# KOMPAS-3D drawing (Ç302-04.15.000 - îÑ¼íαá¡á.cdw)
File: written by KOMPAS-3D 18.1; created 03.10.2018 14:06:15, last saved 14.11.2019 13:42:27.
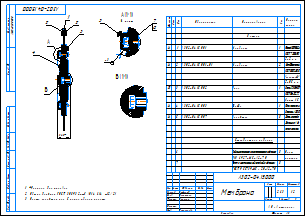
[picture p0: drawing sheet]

Sheet 1: A3, landscape

Document properties: Автор: Милов; Масса: 2.62614; Полное имя файла: ..\А302-01.15.000 - Мембрана.a3d

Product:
- Part/product: (unnamed)
  - Component: Мембрана  | designation А302-04.15.001  | pos. 1  | Раздел спецификации: Детали; Форматы листов документа: А4; Примечание: Пластина ІФ-IІ ТМКЩ-C-4 / ГОСТ 7338-90 / S=2 мм
  - Component: Мембрана  | designation А302-04.15.001-01  | pos. 2  | Раздел спецификации: Детали; Форматы листов документа: А4; Примечание: Лист Фторопласт-4 /  ГОСТ 10007-80 Е / "каленный" / S=0,5 мм
  - Component: Упор  | designation А302-04.15.002  | pos. 3  | Раздел спецификации: Детали; Форматы листов документа: А3; Примечание: Сталь 12Х18Н10Т / ГОСТ 5632-72 / Лист 15
  - Component: Шайба  | designation А302-04.15.003  | pos. 4  | Раздел спецификации: Детали; Форматы листов документа: А4; Примечание: Полипропилен / Стержень @2~300
  - Component: Заглушка  | designation А302-04.15.007  | pos. 5  | Раздел спецификации: Детали; Форматы листов документа: А4; Примечание: Деталь заготовка  / Заглушка @2~16 / полипропилен
  - Component: Гайка шестигранная самостопорящаяся с фланцем / DIN 6927-M5-A2-70  | pos. 6  | Раздел спецификации: Стандартные изделия; Примечание: Нерж. / насечки
  - Component: Болт с шестигранной головкой с фланцем  / ГОСТ Р 55739-М5 x 20-A2-70  | pos. 7  | Раздел спецификации: Стандартные изделия

Title block, sheet 1: Наименование: Мембрана; designation: А302-04.15.000; Масса: 2,63; scale: 1:2; Количество листов документа: 1; organisation: АО «Астерион»; Форматы листов документа: A3; stored path: \\192.168.87.28\Konstructor_doc\Мембранные насосы\Мембранный электропривод\А302-00.00.000 - ASTRA-302 (МЭ200)\3Д ПВХ\А302-01.15.000 - Мембрана.cdw; Разработал: Лифлянд; Проверил: Борисенко; Т. контр.: Лучихин; Утвердил: Григорьева

Views: Вид 1, Местный разрез 1, Вид:2, Выносной элемент 3, Выносной элемент А, Выносной элемент, Выносной элемент Б
Referenced files in D:\Мембранные насосы\Мембранный электропривод\А302-00.00.000 - ASTRA-302 (МЭ200)\3Д ПВХ\: А302-01.15.001-01- Мембрана.m3d, А302-01.15.007 - Заглушка.m3d, А302-01.15.001 - Мембрана.m3d, А302-01.15.002 - Упор.a3d, А302-01.15.003 - Шайба.m3d, А302-01.15.000 - Мембрана.a3d, А302-01.15.001 - Мембрана.cdw, А302-01.15.002 - Упор.m3d, А302-01.15.008 - Кольцо плоское Ф4.m3d, А302-01.15.008 - Кольцо плоское уплотнительное 5-13-10 Ф4.cdw, А302-01.15.009 - Кольцо плоское Ф4.m3d, А302-01.15.007 - Заглушка.cdw, А302-01.15.011 - Заглушка резьбовая.m3d, А302-01.15.011 - Заглушка резьбовая.cdw
Referenced files in Z:\Мембранные насосы\Мембранный электропривод\А302-00.00.000 - ASTRA-302 (МЭ200)\3Д ПВХ\: А302-01.15.000 - Мембрана.a3d, А302-01.15.008 - Кольцо плоское Ф4.m3d
Referenced files in D:\2 Стандартные изделия 3D\Гайки\DIN 6927\: Гайка шестигранная самостопорящаяся с фланцем DIN 6927-M5 - A2-70.m3d
Referenced files in \\192.168.87.28\Konstructor_doc\Мембранные насосы\Мембранный электропривод\А302-00.00.000 - ASTRA-302 (МЭ200)\3Д ПВХ\: А302-01.15.011 - Заглушка резьбовая.cdw
Referenced files in D:\Мембранные насосы\Мембранный электропривод\А302-00.00.000 - ASTRA-302 (МЭ200)\А302-04.00.000 - Мембранный насос ASTRA-302-PP\: А302-02.15.002 - Упор.cdw
Referenced files in C:\Program Files\ASCON\KOMPAS-3D v18\Libs\PartLib\DATA\VAULT\methods\kompas\3d\: PLib_Bolt_1_ISO_1100.m3d, PLib_Nut_ISO_1100.m3d
Referenced files in C:\Program Files\ASCON\KOMPAS-3D V16\Libs\PartLib\DATA\vault\Methods\Kompas\3D\: PLib_Nut_ISO_1100.m3d, PLib_Bolt_1_ISO_1100.m3d
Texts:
  Шайба
  Упор
  Болт с шестигранной головкой с фланцем
  ГОСТ Р  55739-М5 x 25-A2-70
  ГОСТ
  Нерж.
  Нержавеющая сталь
  Гайка шестигранная самостопорящаяся с фланцем
  DIN 6927-M5-A2-70
  Гайка
  шестигранная
  самостопорящаяся
  фланцем
  DIN
  насечки
  Нерж. / насечки
  Кольцо плоское
  уплотнительное 5-13-10 Ф4
  Кольцо плоское  / уплотнительное 5-13-10 Ф4
  ГОСТ Р  55739-М8 x 30-A2-70
  Кольцо плоское Ф4
  Заглушка
  Заглушка резьбовая
  Лента ФУМ
  Лента
  ФУМ
  3D_Doc-graphic.lyt,1.000000-4294967295-203648116615
  Болт с шестигранной головкой с фланцем ГОСТ Р 55739-М5 x 20-A2-70
  Болт
  шестигранной
  головкой
  Пластина ІФ-IІ ТМКЩ-C-4
  ГОСТ 7338-90
  Пластина ІФ-IІ ТМКЩ-C-4 / ГОСТ 7338-90 / S=2 мм
  Лист Фторопласт-4
  ГОСТ 10007-80 Е
  "каленный"
  Лист Фторопласт-4 /  ГОСТ 10007-80 Е / "каленный" / S=0,5 мм
  Сталь 12Х18Н10Т
  ГОСТ 5632-72
  Лист 15
  Сталь 12Х18Н10Т / ГОСТ 5632-72 / Лист 15
  Полипропилен
  Стержень  300
  Полипропилен / Стержень @2~300
  Деталь заготовка
  Заглушка  16
  полипропилен
  Деталь заготовка  / Заглушка @2~16 / полипропилен
  ГОСТ Р 55739-М5 x 20-A2-70
  Болт с шестигранной головкой с фланцем ГОСТ Р 55739-М5 x 25-A2-70
  Гайка шестигранная с фланцем ГОСТ Р ИСО 4161 - M5 - A2-70
  Гайка шестигранная самостопорящаяся с фланцем / DIN 6927-M5-A2-70
  Болт с шестигранной головкой с фланцем ГОСТ Р 55739-М8 x 16-A2-70
Dimensions and other numbers on the sheet: 2; 1; 3; 4; 36,5; 8 мест; 5; 7; 8; 10; 9; 6; 11; 12; 100; 41; 48; 1:2; 2,63

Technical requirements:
  *Размеры для справок.
  Общие допуски ГОСТ 30893.2-mK (H14, h14,  t2/2).
  Паять заглушки поз. 5 после сборки пакета.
